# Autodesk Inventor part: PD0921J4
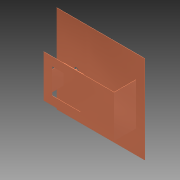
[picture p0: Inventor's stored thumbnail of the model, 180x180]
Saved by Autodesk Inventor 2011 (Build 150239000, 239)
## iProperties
Created: 2014-07
Part Number: PD0921J4
Document SubType Name: Modeling
Designer: Evgeny
Density: 1 g/cm^3
Author: Evgeny
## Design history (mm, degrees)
sketch "Эскиз1"
  geometry: L1 (-75, 37.5)-(50, 37.5); L2 (50, 37.5)-(50, -37.5); L3 (50, -37.5)-(-75, -37.5); L4 (-75, -37.5)-(-75, 37.5); L5 (-10, 22.5)-(-60, 22.5); L6 (-60, 22.5)-(-60, -22.5); L7 (-60, -22.5)-(-10, -22.5); L8 (-10, -22.5)-(-10, 22.5); 1 further point
  constraints: 16 end point, 4 parallel, 2 horizontal, 2 perpendicular
  dimensions: "d0" = 125 distance between parallel lines of L2 L4; "d1" = 75 distance between parallel lines of L3 L1; "d2" = 37.5 distance from line of L3 point (0, 0); "d3" = 75 distance from line of L4 point (0, 0); "d4" = 45 distance between parallel lines of L7 L5; "d5" = 22.5 distance from line of point (0, 0) L5; "d6" = 50 distance between parallel lines of L6 L8; "d7" = 15 distance between parallel lines of L4 L6
extrude "Выдавливание1" new body sketch "Эскиз1" distance "d8" = 0.5; taper "d9" = 0 deg
sketch "Эскиз2"
  geometry: L1 (-50, -37.5)-(75, -37.5) reference; L2 (-50, 37.5)-(-49.5, 37.5); L3 (-49.5, 37.5)-(-49.5, -37.5); L4 (-49.5, -37.5)-(-50, -37.5); L5 (-50, -37.5)-(-50, 37.5); 1 further point
  constraints: 8 end point, 2 parallel, 1 horizontal, 1 perpendicular, 1 point on line
  dimensions: "d10" = 0.5 distance between parallel lines of L5 L3
extrude "Выдавливание2" join sketch "Эскиз2" distance "d11" = 38; taper "d12" = 0 deg
sketch "Эскиз3"
  geometry: L1 (60, 22.5)-(60, -22.5) reference; L2 (60, 17.5)-(60.5, 17.5); L3 (60.5, 17.5)-(60.5, -17.5); L4 (60.5, -17.5)-(60, -17.5); L5 (60, -17.5)-(60, 17.5); 1 further point
  constraints: 8 end point, 2 parallel, 1 horizontal, 1 perpendicular, 1 point on line
  dimensions: "d13" = 35 distance from line of L4 L2.end; "d14" = 0.5 distance between parallel lines of L1 L3; "d15" = 17.5 distance from line of L4 point (0, 0)
extrude "Выдавливание3" join sketch "Эскиз3" distance "d16" = 20; taper "d17" = 0 deg
sketch "Эскиз4"
  geometry: L1 (60.5, 17.5)-(60.5, -17.5) reference; L2 (60.5, 17.5)-(25, 17.5); L3 (25, 17.5)-(25, -17.5); L4 (25, -17.5)-(60.5, -17.5); L5 (60.5, -17.5)-(60.5, 17.5); 1 further point
  constraints: 8 end point, 2 parallel, 1 horizontal, 1 perpendicular
  dimensions: "d18" = 35 distance between parallel lines of L4 L2; "d19" = 35.5 distance between parallel lines of L1 L3
extrude "Выдавливание4" join sketch "Эскиз4" distance "d20" = 0.5; taper "d21" = 0 deg
sketch "Эскиз5"
  geometry: L1 (60.5, 17.5)-(60.5, -17.5) reference; C1 r 1.35 at (55.5, 0); 1 further point
  constraints: 1 centre point
  dimensions: "d22" = 2.7 diameter of C1; "d23" = 5 distance from line of L1 C1.centre
extrude "Выдавливание5" join sketch "Эскиз5" distance "d24" = 18.5; taper "d25" = 0 deg
sketch "Эскиз6"
  geometry: L1 (-50, 37.5)-(-49.5, 37.5) reference; L2 (-50, -37.5)-(-50, 37.5) reference; L3 (-65.5, 78)-(90.5, 78); L4 (90.5, 78)-(90.5, -78); L5 (90.5, -78)-(-65.5, -78); L6 (-65.5, -78)-(-65.5, 78); C1 r 4 at (55.461, 0)
  constraints: 8 end point, 2 parallel, 1 centre point, 1 horizontal, 1 perpendicular
  dimensions: "d26" = 156 distance between parallel lines of L5 L3; "d27" = 156 distance between parallel lines of L4 L6; "d30" = 15.5 distance between parallel lines of L2 L6; "d31" = 40.5 distance between parallel lines of L3 L1; "d32" = 8 diameter of C1; "d33" = 105.46063 distance from line of L2 C1.centre
extrude "Выдавливание6" join sketch "Эскиз6" distance "d34" = 0.5; taper "d35" = 0 deg
node "Твердое тело1"
